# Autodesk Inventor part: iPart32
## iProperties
Created: 2005-03
Part Number: iPart32
Document SubType Name: Modeling
Designer: CADCIM
Manufacturer: Standard
Standards Organization: Custom
Author: CADCIM
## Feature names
1. Derived Body1 [Tagging]
